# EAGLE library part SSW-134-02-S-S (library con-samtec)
THROUGH-HOLE .025" SQ POST SOCKET Source: Samtec SSW.pdf
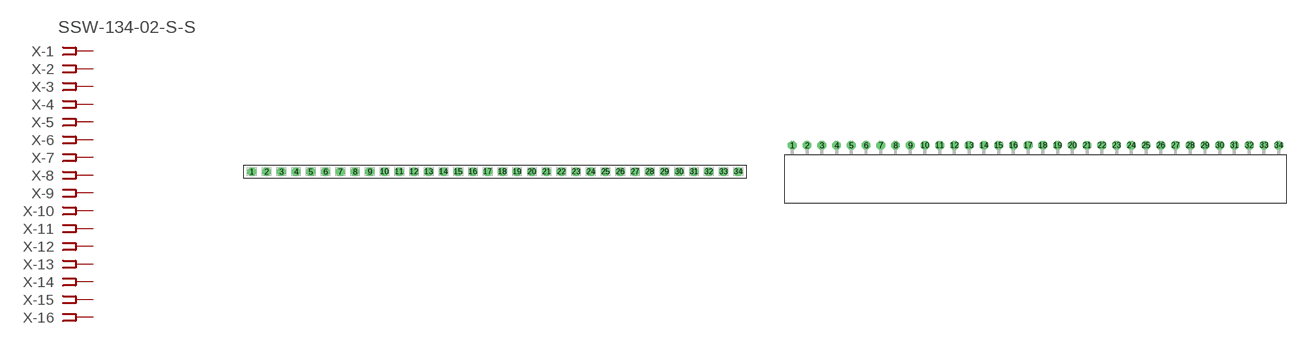
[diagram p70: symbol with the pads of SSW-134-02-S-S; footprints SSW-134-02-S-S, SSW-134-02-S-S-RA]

Designator prefix X; gates -1=FPINV -2=FPIN -3=FPIN -4=FPIN -5=FPIN -6=FPIN -7=FPIN -8=FPIN -9=FPIN -10=FPIN -11=FPIN -12=FPIN -13=FPIN -14=FPIN -15=FPIN -16=FPIN -17=FPIN -18=FPIN -19=FPIN -20=FPIN -21=FPIN -22=FPIN -23=FPIN -24=FPIN -25=FPIN -26=FPIN -27=FPIN -28=FPIN -29=FPIN -30=FPIN -31=FPIN -32=FPIN -33=FPIN -34=FPIN

## SSW-134-02-S-S (MPN: SSW-134-02-S-S; OC_FARNELL: unknown; OC_NEWARK: 11P9871)  [SSW-134-02-S-S]
1  -1:1  pas
2  -2:1  pas
3  -3:1  pas
4  -4:1  pas
5  -5:1  pas
6  -6:1  pas
7  -7:1  pas
8  -8:1  pas
9  -9:1  pas
10  -10:1  pas
11  -11:1  pas
12  -12:1  pas
13  -13:1  pas
14  -14:1  pas
15  -15:1  pas
16  -16:1  pas
17  -17:1  pas
18  -18:1  pas
19  -19:1  pas
20  -20:1  pas
21  -21:1  pas
22  -22:1  pas
23  -23:1  pas
24  -24:1  pas
25  -25:1  pas
26  -26:1  pas
27  -27:1  pas
28  -28:1  pas
29  -29:1  pas
30  -30:1  pas
31  -31:1  pas
32  -32:1  pas
33  -33:1  pas
34  -34:1  pas

## SSW-134-02-S-S-RA (MPN: SSW-134-02-S-S-RA; OC_FARNELL: unknown; OC_NEWARK: 11P9872)  [SSW-134-02-S-S-RA]
Pads as for SSW-134-02-S-S

## Footprint SSW-134-02-S-S (pad centres in mm)
THROUGH-HOLE .025" SQ POST SOCKET Source: Samtec SSW.pdf
drill 1 pad 1.5 octagon: 1 -41.91,0; 2 -39.37,0; 3 -36.83,0; 4 -34.29,0; 5 -31.75,0; 6 -29.21,0; 7 -26.67,0; 8 -24.13,0; 9 -21.59,0; 10 -19.05,0; 11 -16.51,0; 12 -13.97,0; 13 -11.43,0; 14 -8.89,0; 15 -6.35,0; 16 -3.81,0; 17 -1.27,0; 18 1.27,0; 19 3.81,0; 20 6.35,0; 21 8.89,0; 22 11.43,0; 23 13.97,0; 24 16.51,0; 25 19.05,0; 26 21.59,0; 27 24.13,0; 28 26.67,0; 29 29.21,0; 30 31.75,0; 31 34.29,0; 32 36.83,0; 33 39.37,0; 34 41.91,0

## Footprint SSW-134-02-S-S-RA (pad centres in mm)
THROUGH-HOLE .025" SQ POST SOCKET Source: Samtec SSW.pdf
drill 1 pad 1.5 octagon: 1 -41.91,1.524; 2 -39.37,1.524; 3 -36.83,1.524; 4 -34.29,1.524; 5 -31.75,1.524; 6 -29.21,1.524; 7 -26.67,1.524; 8 -24.13,1.524; 9 -21.59,1.524; 10 -19.05,1.524; 11 -16.51,1.524; 12 -13.97,1.524; 13 -11.43,1.524; 14 -8.89,1.524; 15 -6.35,1.524; 16 -3.81,1.524; 17 -1.27,1.524; 18 1.27,1.524; 19 3.81,1.524; 20 6.35,1.524; 21 8.89,1.524; 22 11.43,1.524; 23 13.97,1.524; 24 16.51,1.524; 25 19.05,1.524; 26 21.59,1.524; 27 24.13,1.524; 28 26.67,1.524; 29 29.21,1.524; 30 31.75,1.524; 31 34.29,1.524; 32 36.83,1.524; 33 39.37,1.524; 34 41.91,1.524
